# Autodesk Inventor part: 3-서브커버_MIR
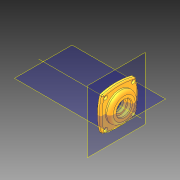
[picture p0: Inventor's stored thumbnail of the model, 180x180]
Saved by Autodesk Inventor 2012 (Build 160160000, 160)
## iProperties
Created: 2012-07
Part Number: 3-서브커버_MIR
Material: Default
Document SubType Name: Modeling
Designer: JANG KYOUNG-IL
Density: 1 g/cm^3
Author: JANG KYOUNG-IL
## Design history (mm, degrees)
derived "3-서브커버.ipt"
  node "작업 평면3"
  node "작업축1"
  node "작업점1"
feature "솔리드3::3-서브커버.ipt" dims "d0" = 10
sketch "스케치12"
  geometry: L1 (46.5, 57.5)-(72.5, 57.5) reference; L2 (46.5, 90)-(55.5, 90) reference; L3 (55.5, 90)-(55.5, 87.5) reference; L4 (55.5, 87.5)-(72.5, 87.5) reference; L5 (72.5, 87.5)-(72.5, 73.5) reference; L6 (72.5, 73.5)-(64.2, 73.5) reference; L7 (64.2, 73.5)-(64.2, 70) reference; L8 (64.2, 70)-(58.5, 70) reference; L9 (58.5, 70)-(58.5, 77.5) reference; L10 (58.5, 77.5)-(46.5, 77.5) reference; L11 (46.5, 77.5)-(46.5, 90) reference; 1 further point
sketch "스케치13"
  geometry: L1 (35.002, 92.502)-(-35.002, 92.502) reference; L2 (-35.002, 92.502)-(-35.002, 22.498) reference; L3 (-35.002, 22.498)-(35.002, 22.498) reference; L4 (35.002, 22.498)-(35.002, 92.502) reference; C1 r 20 at (0, 57.5) reference; A1 r 125.055 centre (0, -27.555) between (35.002, 92.502) and (-35.002, 92.502) reference; A2 r 125.055 centre (0, 142.555) between (-35.002, 22.498) and (35.002, 22.498) reference; A3 r 125.055 centre (-85.055, 57.5) between (35.002, 22.498) and (35.002, 92.502) reference; A4 r 125.055 centre (85.055, 57.5) between (-35.002, 92.502) and (-35.002, 22.498) reference; 4 further points
sketch "스케치14"
  geometry: L1 (57.5, 0)-(99, 0) reference; A1 r 41.5 centre (57.5, 0) between (86.845, 29.345) and (99, 0) reference; 2 further points
node "작업 평면2"
tag "피쳐 태그1"
node "솔리드1"
